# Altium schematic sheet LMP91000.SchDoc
size 246 x 182 mm
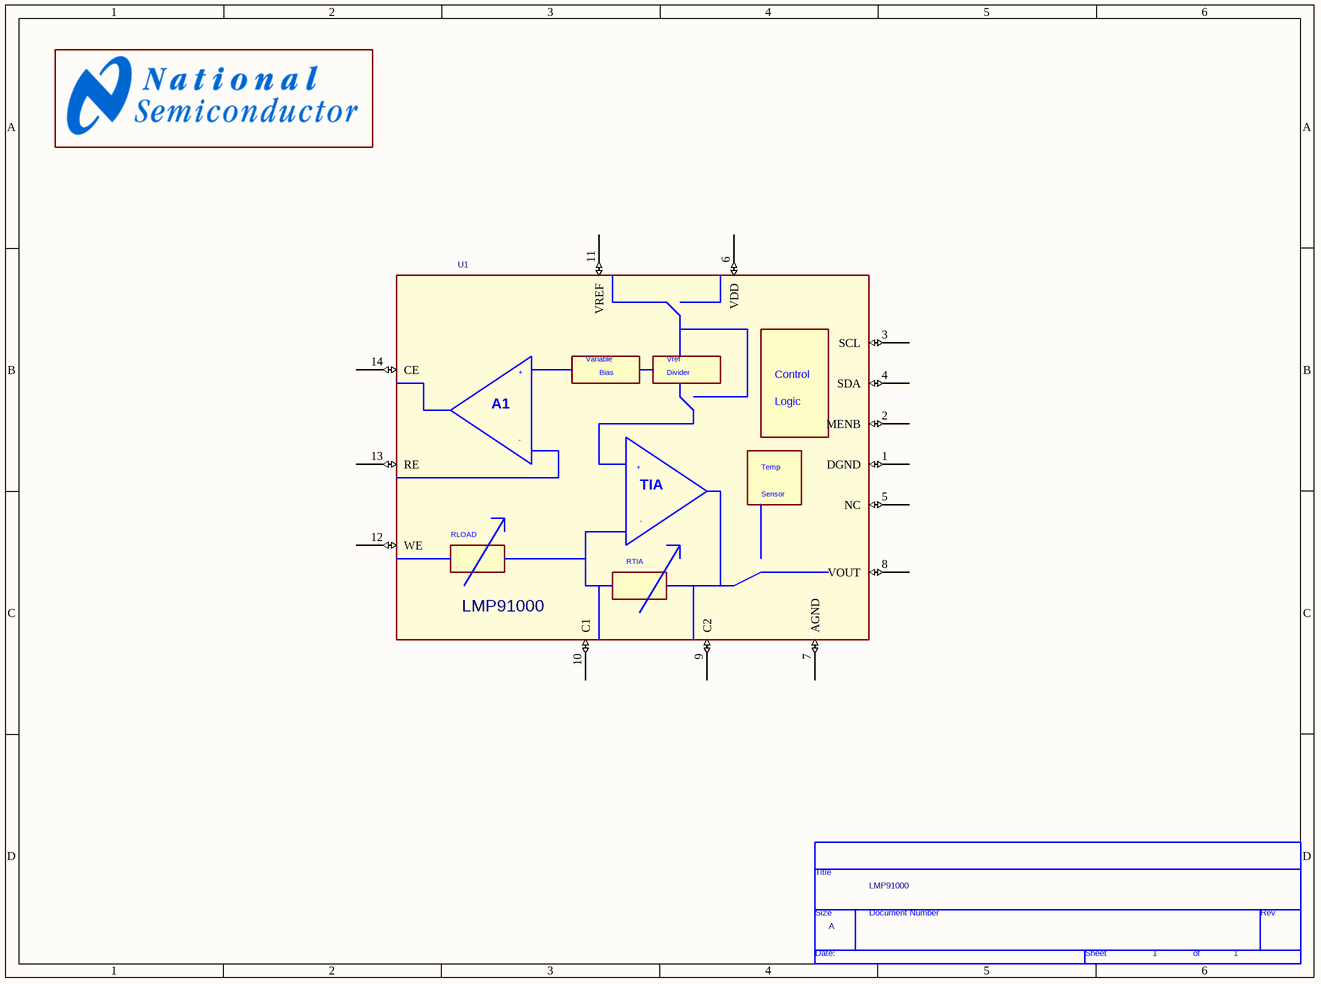
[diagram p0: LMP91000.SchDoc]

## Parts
*  Title: LMP91000  Page Size: A  Page Number: 1  (hidden comment: TitleBlock0)  (graphical)
U1  LMP91000

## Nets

Not connected (* = marked no-connect by the designer): U1 1(DGND) 2(MENB) 3(SCL) 4(SDA) 5(NC) 6(VDD) 7(AGND) 8(VOUT) 9(C2) 10(C1) 11(VREF) 12(WE) 13(RE) 14(CE)

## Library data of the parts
* = TitleBlock0: OrgName: AMITAVA BANERJEE; OrgAddr1: NATIONAL SEMICONDUCTOR
U1 = LMP91000: PSpiceTemplate: X^@REFDES %DGND %MENB %SCL %SDA %NC %VDD %AGND %VOUT %C2 %C1 %VREF %WE %RE %CE @MODEL; BiasValue Power: 0W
